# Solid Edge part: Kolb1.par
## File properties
Author: KULL
Template: Iso Metric Part.par
Last saved by: KULL
Revision: 25
Application: Solid Edge
Accuracy: 0,990
Face Style: Model Default
Fill Style: Normal
Coef. of Thermal Exp: 0.0
Thermal Conductivity: 0.0
Specific Heat: 0.0
Modulus of Elasticity: 0.0
Poisson's Ratio: 0.0
Yield Stress: 0.0
Ultimate Stress: 0.0
Elongation: 0.0
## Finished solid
Body 1: solid body, 82 faces, 132 edges, 48 vertices.
  Faces by surface: blend 38, torus 17, cylinder 16, plane 9, sphere 2
  Edges by curve: intersection 68, circle 60, ellipse 4
Bounding box of the edges (mm; curved faces can reach further): 12.000 x 12.816 x 12.108, from (-6, -8.6833, -3.3805) to (6, 4.1324, 8.7275).
Cylindrical faces by radius (mm): R0.4 x2, R0.6 x1, R1.5 x3, R2 x2, R5 x1, R5.5 x2, R6 x3, R16.406 x2
Toroidal faces (ring radius, tube radius in mm): R1.8 r0.2 x2, R2.5 r1 x2, R5.3419 r0.3 x1, R5.4 r0.4 x2, R5.6 r0.1 x4, R5.6 r0.4 x2, R5.9 r0.1 x4
Spherical faces by radius (mm): R20.2136 x1, R21.2136 x1
Planar faces by outward normal: +x 1, -x 1, oblique 7
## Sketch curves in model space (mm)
line (9.7412, 0, 0) -> (-9.7412, 0, 0)
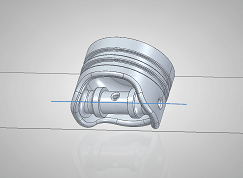
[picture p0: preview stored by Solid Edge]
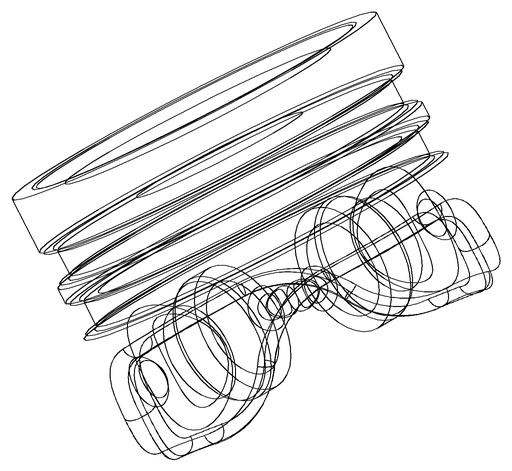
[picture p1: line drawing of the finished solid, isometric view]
